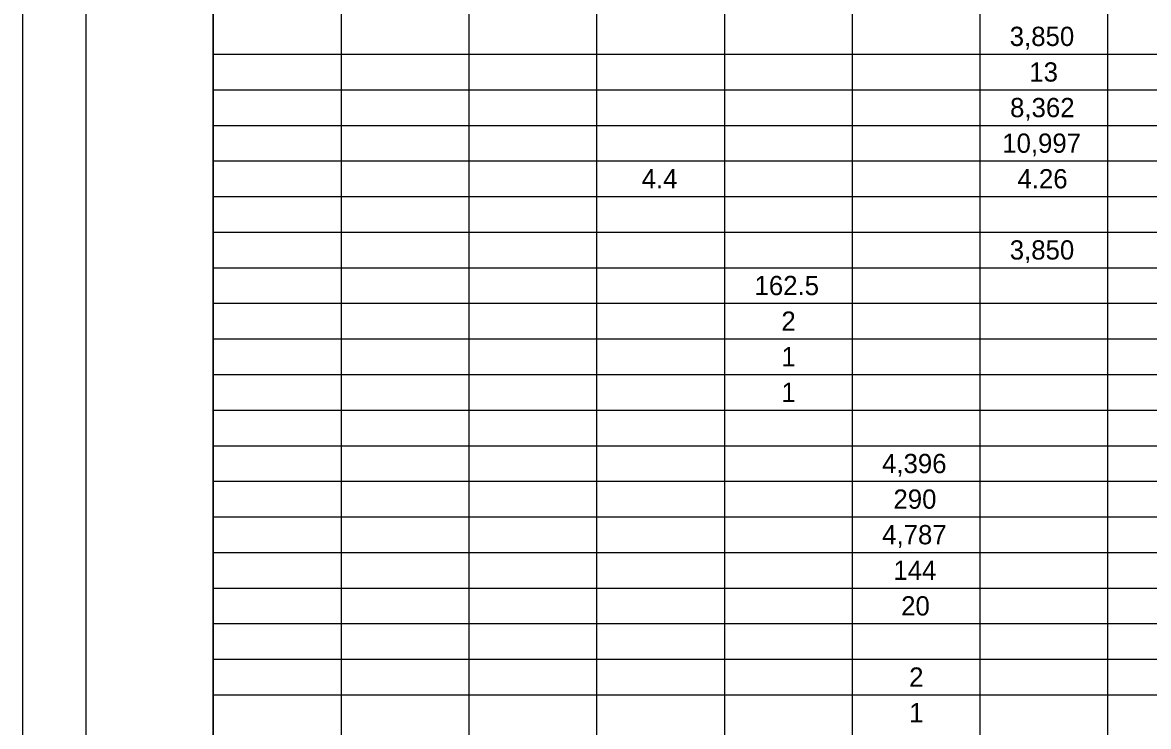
# Model space of a CAD drawing. Extents: x 0 to 34, y 0 to 22.
# Drawn here: x 0 to 8.85, y 10.89 to 16.43 of the extents above; entities that cross this region are included whole.
import ezdxf

# ---------------------------------------------------------------- set-up
doc = ezdxf.new("R2010")
doc.units = 0
for name, color, linetype in [('Default', 7, 'Continuous'), ('SH_Border', 7, 'Continuous'), ('SH_Cut_Line', 7, 'Continuous')]:
    doc.layers.add(name, color=color, linetype=linetype)

msp = doc.modelspace()

# ---------------------------------------------------------------- linework, layer by layer
at = {"layer": 'Default'}
for p, q in [((1.5, 21.5), (1.5, 0.5)), ((2.5046, 20.94), (2.5046, 0.5)), ((3.5092, 20.94), (3.5092, 0.5)), ((4.5138, 20.94), (4.5138, 0.5)), ((5.5184, 20.94), (5.5184, 0.5)), ((6.5229, 20.94), (6.5229, 0.5)), ((7.5275, 20.94), (7.5275, 0.5)), ((8.5321, 20.94), (8.5321, 0.5)), ((1.5, 16.18), (32, 16.18)), ((1.5, 15.9), (32, 15.9)), ((1.5, 15.62), (32, 15.62)), ((1.5, 15.34), (32, 15.34)), ((1.5, 15.06), (32, 15.06)), ((1.5, 14.78), (32, 14.78)), ((1.5, 14.5), (32, 14.5)), ((1.5, 14.22), (32, 14.22)), ((1.5, 13.94), (32, 13.94)), ((1.5, 13.66), (32, 13.66)), ((1.5, 13.38), (32, 13.38)), ((1.5, 13.1), (32, 13.1)), ((1.5, 12.82), (32, 12.82)), ((1.5, 12.54), (32, 12.54)), ((1.5, 12.26), (32, 12.26)), ((1.5, 11.98), (32, 11.98)), ((1.5, 11.7), (32, 11.7)), ((1.5, 11.42), (32, 11.42)), ((1.5, 11.14), (32, 11.14))]:
    msp.add_line(p, q, dxfattribs=at)
at = {"layer": 'SH_Border'}
for points in [[(0.5, 21.5), (1.5, 21.5), (1.5, 0.5), (0.5, 0.5)], [(1.5, 21.5), (33.5, 21.5), (33.5, 0.5), (1.5, 0.5)]]:
    msp.add_lwpolyline(points, close=True, dxfattribs=at)
at = {"layer": 'SH_Cut_Line'}
msp.add_lwpolyline([(0, 0), (34, 0), (34, 22), (0, 22)], close=True, dxfattribs=at)

# ---------------------------------------------------------------- texts
at = {"layer": 'Default'}
for s, height, p in [('3,850', 0.15153, (7.7623, 16.2442)), ('13', 0.15153, (7.9162, 15.9642)), ('8,362', 0.15153, (7.7648, 15.6842)), ('10,997', 0.15153, (7.7032, 15.4042)), ('4.4', 0.15153, (4.8684, 15.1242)), ('4.26', 0.15153, (7.823, 15.1242)), ('3,850', 0.15153, (7.7623, 14.5642)), ('162.5', 0.15153, (5.7556, 14.2842)), ('2', 0.1515, (5.9668, 14.0042)), ('1', 0.1515, (5.9667, 13.7242)), ('1', 0.1515, (5.9667, 13.4442)), ('4,396', 0.15153, (6.7583, 12.8842)), ('290', 0.15153, (6.848, 12.6042)), ('4,787', 0.15153, (6.7591, 12.3242)), ('144', 0.15153, (6.8473, 12.0442)), ('20', 0.15153, (6.9084, 11.7642)), ('2', 0.1515, (6.9714, 11.2042)), ('1', 0.1515, (6.9713, 10.9242))]:
    msp.add_text(s, height=height, dxfattribs=at).set_placement(p)

doc.saveas('drawing.dxf')
